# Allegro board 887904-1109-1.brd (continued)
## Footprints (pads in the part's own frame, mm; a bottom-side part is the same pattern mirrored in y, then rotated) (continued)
PG_VG93K_F_HSM_G1D105_505_ND
  rect 1.626x1.626 smd: A1(-20.32,-3.81) A3(-15.24,-3.81) A5(-10.16,-3.81) A7(-5.08,-3.81) A9(0,-3.81) A11(5.08,-3.81) A13(10.16,-3.81) A15(15.24,-3.81) A17(20.32,-3.81) B2(-17.78,-1.27) B4(-12.7,-1.27) B6(-7.62,-1.27) B8(-2.54,-1.27) B10(2.54,-1.27) B12(7.62,-1.27) B14(12.7,-1.27) B16(17.78,-1.27) C1(-20.32,1.27) C3(-15.24,1.27) C5(-10.16,1.27) C7(-5.08,1.27) C9(0,1.27) C11(5.08,1.27) C13(10.16,1.27) C15(15.24,1.27) C17(20.32,1.27) D2(-17.78,3.81) D4(-12.7,3.81) D6(-7.62,3.81) D8(-2.54,3.81) D10(2.54,3.81) D12(7.62,3.81) D14(12.7,3.81) D16(17.78,3.81)
  round 1.626 smd: A2(-17.78,-3.81) A4(-12.7,-3.81) A6(-7.62,-3.81) A8(-2.54,-3.81) A10(2.54,-3.81) A12(7.62,-3.81) A14(12.7,-3.81) A16(17.78,-3.81) B1(-20.32,-1.27) B3(-15.24,-1.27) B5(-10.16,-1.27) B7(-5.08,-1.27) B9(0,-1.27) B11(5.08,-1.27) B13(10.16,-1.27) B15(15.24,-1.27) B17(20.32,-1.27) C2(-17.78,1.27) C4(-12.7,1.27) C6(-7.62,1.27) C8(-2.54,1.27) C10(2.54,1.27) C12(7.62,1.27) C14(12.7,1.27) C16(17.78,1.27) D3(-15.24,3.81) D5(-10.16,3.81) D7(-5.08,3.81) D9(0,3.81) D11(5.08,3.81) D13(10.16,3.81) D15(15.24,3.81)
PG_VG93K_F_HSM_G1D106_506_ND
  rect 1.626x1.626 smd: A1(-20.32,-3.81) A3(-15.24,-3.81) A5(-10.16,-3.81) A7(-5.08,-3.81) A9(0,-3.81) A11(5.08,-3.81) A13(10.16,-3.81) A15(15.24,-3.81) A17(20.32,-3.81) B2(-17.78,-1.27) B4(-12.7,-1.27) B6(-7.62,-1.27) B8(-2.54,-1.27) B10(2.54,-1.27) B12(7.62,-1.27) B14(12.7,-1.27) B16(17.78,-1.27) C1(-20.32,1.27) C3(-15.24,1.27) C5(-10.16,1.27) C7(-5.08,1.27) C9(0,1.27) C11(5.08,1.27) C13(10.16,1.27) C15(15.24,1.27) C17(20.32,1.27) D2(-17.78,3.81) D4(-12.7,3.81) D6(-7.62,3.81) D8(-2.54,3.81) D10(2.54,3.81) D12(7.62,3.81) D14(12.7,3.81) D16(17.78,3.81)
  round 1.626 smd: A2(-17.78,-3.81) A4(-12.7,-3.81) A6(-7.62,-3.81) A8(-2.54,-3.81) A10(2.54,-3.81) A12(7.62,-3.81) A14(12.7,-3.81) A16(17.78,-3.81) B1(-20.32,-1.27) B3(-15.24,-1.27) B5(-10.16,-1.27) B7(-5.08,-1.27) B9(0,-1.27) B11(5.08,-1.27) B13(10.16,-1.27) B15(15.24,-1.27) B17(20.32,-1.27) C2(-17.78,1.27) C4(-12.7,1.27) C6(-7.62,1.27) C8(-2.54,1.27) C10(2.54,1.27) C12(7.62,1.27) C14(12.7,1.27) C16(17.78,1.27) D3(-15.24,3.81) D5(-10.16,3.81) D7(-5.08,3.81) D9(0,3.81) D11(5.08,3.81) D13(10.16,3.81) D15(15.24,3.81)
PG_VG93K_F_HSM_G1D107_507_ND
  rect 1.626x1.626 smd: A1(-20.32,-3.81) A3(-15.24,-3.81) A5(-10.16,-3.81) A7(-5.08,-3.81) A9(0,-3.81) A11(5.08,-3.81) A13(10.16,-3.81) A15(15.24,-3.81) A17(20.32,-3.81) B2(-17.78,-1.27) B4(-12.7,-1.27) B6(-7.62,-1.27) B8(-2.54,-1.27) B10(2.54,-1.27) B12(7.62,-1.27) B14(12.7,-1.27) B16(17.78,-1.27) C1(-20.32,1.27) C3(-15.24,1.27) C5(-10.16,1.27) C7(-5.08,1.27) C9(0,1.27) C11(5.08,1.27) C13(10.16,1.27) C15(15.24,1.27) C17(20.32,1.27) D2(-17.78,3.81) D4(-12.7,3.81) D6(-7.62,3.81) D8(-2.54,3.81) D10(2.54,3.81) D12(7.62,3.81) D14(12.7,3.81) D16(17.78,3.81)
  round 1.626 smd: A2(-17.78,-3.81) A4(-12.7,-3.81) A6(-7.62,-3.81) A8(-2.54,-3.81) A10(2.54,-3.81) A12(7.62,-3.81) A14(12.7,-3.81) A16(17.78,-3.81) B1(-20.32,-1.27) B3(-15.24,-1.27) B5(-10.16,-1.27) B7(-5.08,-1.27) B9(0,-1.27) B11(5.08,-1.27) B13(10.16,-1.27) B15(15.24,-1.27) B17(20.32,-1.27) C2(-17.78,1.27) C4(-12.7,1.27) C6(-7.62,1.27) C8(-2.54,1.27) C10(2.54,1.27) C12(7.62,1.27) C14(12.7,1.27) C16(17.78,1.27) D3(-15.24,3.81) D5(-10.16,3.81) D7(-5.08,3.81) D9(0,3.81) D11(5.08,3.81) D13(10.16,3.81) D15(15.24,3.81)
PG_VG93K_F_HSM_G3D117_517_ND
  rect 1.626x1.626 smd: A1(-20.32,-3.81) A3(-15.24,-3.81) A5(-10.16,-3.81) A7(-5.08,-3.81) A9(0,-3.81) A11(5.08,-3.81) A13(10.16,-3.81) A15(15.24,-3.81) A17(20.32,-3.81) B2(-17.78,-1.27) B4(-12.7,-1.27) B6(-7.62,-1.27) B8(-2.54,-1.27) B10(2.54,-1.27) B12(7.62,-1.27) B14(12.7,-1.27) B16(17.78,-1.27) C1(-20.32,1.27) C3(-15.24,1.27) C5(-10.16,1.27) C7(-5.08,1.27) C9(0,1.27) C11(5.08,1.27) C13(10.16,1.27) C15(15.24,1.27) C17(20.32,1.27) D2(-17.78,3.81) D4(-12.7,3.81) D6(-7.62,3.81) D8(-2.54,3.81) D10(2.54,3.81) D12(7.62,3.81) D14(12.7,3.81) D16(17.78,3.81)
  round 1.626 smd: A2(-17.78,-3.81) A4(-12.7,-3.81) A6(-7.62,-3.81) A8(-2.54,-3.81) A10(2.54,-3.81) A12(7.62,-3.81) A14(12.7,-3.81) A16(17.78,-3.81) B1(-20.32,-1.27) B3(-15.24,-1.27) B5(-10.16,-1.27) B7(-5.08,-1.27) B9(0,-1.27) B11(5.08,-1.27) B13(10.16,-1.27) B15(15.24,-1.27) B17(20.32,-1.27) C2(-17.78,1.27) C4(-12.7,1.27) C6(-7.62,1.27) C8(-2.54,1.27) C10(2.54,1.27) C12(7.62,1.27) C14(12.7,1.27) C16(17.78,1.27) D3(-15.24,3.81) D5(-10.16,3.81) D7(-5.08,3.81) D9(0,3.81) D11(5.08,3.81) D13(10.16,3.81) D15(15.24,3.81)
PG_VG93K_F_HSM_G3D118_518_ND
  rect 1.626x1.626 smd: A1(-20.32,-3.81) A3(-15.24,-3.81) A5(-10.16,-3.81) A7(-5.08,-3.81) A9(0,-3.81) A11(5.08,-3.81) A13(10.16,-3.81) A15(15.24,-3.81) A17(20.32,-3.81) B2(-17.78,-1.27) B4(-12.7,-1.27) B6(-7.62,-1.27) B8(-2.54,-1.27) B10(2.54,-1.27) B12(7.62,-1.27) B14(12.7,-1.27) B16(17.78,-1.27) C1(-20.32,1.27) C3(-15.24,1.27) C5(-10.16,1.27) C7(-5.08,1.27) C9(0,1.27) C11(5.08,1.27) C13(10.16,1.27) C15(15.24,1.27) C17(20.32,1.27) D2(-17.78,3.81) D4(-12.7,3.81) D6(-7.62,3.81) D8(-2.54,3.81) D10(2.54,3.81) D12(7.62,3.81) D14(12.7,3.81) D16(17.78,3.81)
  round 1.626 smd: A2(-17.78,-3.81) A4(-12.7,-3.81) A6(-7.62,-3.81) A8(-2.54,-3.81) A10(2.54,-3.81) A12(7.62,-3.81) A14(12.7,-3.81) A16(17.78,-3.81) B1(-20.32,-1.27) B3(-15.24,-1.27) B5(-10.16,-1.27) B7(-5.08,-1.27) B9(0,-1.27) B11(5.08,-1.27) B13(10.16,-1.27) B15(15.24,-1.27) B17(20.32,-1.27) C2(-17.78,1.27) C4(-12.7,1.27) C6(-7.62,1.27) C8(-2.54,1.27) C10(2.54,1.27) C12(7.62,1.27) C14(12.7,1.27) C16(17.78,1.27) D3(-15.24,3.81) D5(-10.16,3.81) D7(-5.08,3.81) D9(0,3.81) D11(5.08,3.81) D13(10.16,3.81) D15(15.24,3.81)
PG_VG93K_F_HSM_G3D119_519_ND
  rect 1.626x1.626 smd: A1(-20.32,-3.81) A3(-15.24,-3.81) A5(-10.16,-3.81) A7(-5.08,-3.81) A9(0,-3.81) A11(5.08,-3.81) A13(10.16,-3.81) A15(15.24,-3.81) A17(20.32,-3.81) B2(-17.78,-1.27) B4(-12.7,-1.27) B6(-7.62,-1.27) B8(-2.54,-1.27) B10(2.54,-1.27) B12(7.62,-1.27) B14(12.7,-1.27) B16(17.78,-1.27) C1(-20.32,1.27) C3(-15.24,1.27) C5(-10.16,1.27) C7(-5.08,1.27) C9(0,1.27) C11(5.08,1.27) C13(10.16,1.27) C15(15.24,1.27) C17(20.32,1.27) D2(-17.78,3.81) D4(-12.7,3.81) D6(-7.62,3.81) D8(-2.54,3.81) D10(2.54,3.81) D12(7.62,3.81) D14(12.7,3.81) D16(17.78,3.81)
  round 1.626 smd: A2(-17.78,-3.81) A4(-12.7,-3.81) A6(-7.62,-3.81) A8(-2.54,-3.81) A10(2.54,-3.81) A12(7.62,-3.81) A14(12.7,-3.81) A16(17.78,-3.81) B1(-20.32,-1.27) B3(-15.24,-1.27) B5(-10.16,-1.27) B7(-5.08,-1.27) B9(0,-1.27) B11(5.08,-1.27) B13(10.16,-1.27) B15(15.24,-1.27) B17(20.32,-1.27) C2(-17.78,1.27) C4(-12.7,1.27) C6(-7.62,1.27) C8(-2.54,1.27) C10(2.54,1.27) C12(7.62,1.27) C14(12.7,1.27) C16(17.78,1.27) D3(-15.24,3.81) D5(-10.16,3.81) D7(-5.08,3.81) D9(0,3.81) D11(5.08,3.81) D13(10.16,3.81) D15(15.24,3.81)
PG_VG93K_F_HSM_G3D121_521_ND
  rect 1.626x1.626 smd: A1(-20.32,-3.81) A3(-15.24,-3.81) A5(-10.16,-3.81) A7(-5.08,-3.81) A9(0,-3.81) A11(5.08,-3.81) A13(10.16,-3.81) A15(15.24,-3.81) A17(20.32,-3.81) B2(-17.78,-1.27) B4(-12.7,-1.27) B6(-7.62,-1.27) B8(-2.54,-1.27) B10(2.54,-1.27) B12(7.62,-1.27) B14(12.7,-1.27) B16(17.78,-1.27) C1(-20.32,1.27) C3(-15.24,1.27) C5(-10.16,1.27) C7(-5.08,1.27) C9(0,1.27) C11(5.08,1.27) C13(10.16,1.27) C15(15.24,1.27) C17(20.32,1.27) D2(-17.78,3.81) D4(-12.7,3.81) D6(-7.62,3.81) D8(-2.54,3.81) D10(2.54,3.81) D12(7.62,3.81) D14(12.7,3.81) D16(17.78,3.81)
  round 1.626 smd: A2(-17.78,-3.81) A4(-12.7,-3.81) A6(-7.62,-3.81) A8(-2.54,-3.81) A10(2.54,-3.81) A12(7.62,-3.81) A14(12.7,-3.81) A16(17.78,-3.81) B1(-20.32,-1.27) B3(-15.24,-1.27) B5(-10.16,-1.27) B7(-5.08,-1.27) B9(0,-1.27) B11(5.08,-1.27) B13(10.16,-1.27) B15(15.24,-1.27) B17(20.32,-1.27) C2(-17.78,1.27) C4(-12.7,1.27) C6(-7.62,1.27) C8(-2.54,1.27) C10(2.54,1.27) C12(7.62,1.27) C14(12.7,1.27) C16(17.78,1.27) D3(-15.24,3.81) D5(-10.16,3.81) D7(-5.08,3.81) D9(0,3.81) D11(5.08,3.81) D13(10.16,3.81) D15(15.24,3.81)
PG_VG93K_F_HSM_G3D122_522_ND
  rect 1.626x1.626 smd: A1(-20.32,-3.81) A3(-15.24,-3.81) A5(-10.16,-3.81) A7(-5.08,-3.81) A9(0,-3.81) A11(5.08,-3.81) A13(10.16,-3.81) A15(15.24,-3.81) A17(20.32,-3.81) B2(-17.78,-1.27) B4(-12.7,-1.27) B6(-7.62,-1.27) B8(-2.54,-1.27) B10(2.54,-1.27) B12(7.62,-1.27) B14(12.7,-1.27) B16(17.78,-1.27) C1(-20.32,1.27) C3(-15.24,1.27) C5(-10.16,1.27) C7(-5.08,1.27) C9(0,1.27) C11(5.08,1.27) C13(10.16,1.27) C15(15.24,1.27) C17(20.32,1.27) D2(-17.78,3.81) D4(-12.7,3.81) D6(-7.62,3.81) D8(-2.54,3.81) D10(2.54,3.81) D12(7.62,3.81) D14(12.7,3.81) D16(17.78,3.81)
  round 1.626 smd: A2(-17.78,-3.81) A4(-12.7,-3.81) A6(-7.62,-3.81) A8(-2.54,-3.81) A10(2.54,-3.81) A12(7.62,-3.81) A14(12.7,-3.81) A16(17.78,-3.81) B1(-20.32,-1.27) B3(-15.24,-1.27) B5(-10.16,-1.27) B7(-5.08,-1.27) B9(0,-1.27) B11(5.08,-1.27) B13(10.16,-1.27) B15(15.24,-1.27) B17(20.32,-1.27) C2(-17.78,1.27) C4(-12.7,1.27) C6(-7.62,1.27) C8(-2.54,1.27) C10(2.54,1.27) C12(7.62,1.27) C14(12.7,1.27) C16(17.78,1.27) D3(-15.24,3.81) D5(-10.16,3.81) D7(-5.08,3.81) D9(0,3.81) D11(5.08,3.81) D13(10.16,3.81) D15(15.24,3.81)
PG_VG93K_F_HSM_G3D123_523_ND
  rect 1.626x1.626 smd: A1(-20.32,-3.81) A3(-15.24,-3.81) A5(-10.16,-3.81) A7(-5.08,-3.81) A9(0,-3.81) A11(5.08,-3.81) A13(10.16,-3.81) A15(15.24,-3.81) A17(20.32,-3.81) B2(-17.78,-1.27) B4(-12.7,-1.27) B6(-7.62,-1.27) B8(-2.54,-1.27) B10(2.54,-1.27) B12(7.62,-1.27) B14(12.7,-1.27) B16(17.78,-1.27) C1(-20.32,1.27) C3(-15.24,1.27) C5(-10.16,1.27) C7(-5.08,1.27) C9(0,1.27) C11(5.08,1.27) C13(10.16,1.27) C15(15.24,1.27) C17(20.32,1.27) D2(-17.78,3.81) D4(-12.7,3.81) D6(-7.62,3.81) D8(-2.54,3.81) D10(2.54,3.81) D12(7.62,3.81) D14(12.7,3.81) D16(17.78,3.81)
  round 1.626 smd: A2(-17.78,-3.81) A4(-12.7,-3.81) A6(-7.62,-3.81) A8(-2.54,-3.81) A10(2.54,-3.81) A12(7.62,-3.81) A14(12.7,-3.81) A16(17.78,-3.81) B1(-20.32,-1.27) B3(-15.24,-1.27) B5(-10.16,-1.27) B7(-5.08,-1.27) B9(0,-1.27) B11(5.08,-1.27) B13(10.16,-1.27) B15(15.24,-1.27) B17(20.32,-1.27) C2(-17.78,1.27) C4(-12.7,1.27) C6(-7.62,1.27) C8(-2.54,1.27) C10(2.54,1.27) C12(7.62,1.27) C14(12.7,1.27) C16(17.78,1.27) D3(-15.24,3.81) D5(-10.16,3.81) D7(-5.08,3.81) D9(0,3.81) D11(5.08,3.81) D13(10.16,3.81) D15(15.24,3.81)
PG_VG93K_PF_DPS32_G8D225
  rect 1.778x1.778 hole 0.711: A1(20.32,3.81) A3(15.24,3.81) A5(10.16,3.81) A7(5.08,3.81) A9(0,3.81) A11(-5.08,3.81) A13(-10.16,3.81) A15(-15.24,3.81) B2(17.78,1.27) B4(12.7,1.27) B6(7.62,1.27) B8(2.54,1.27) B10(-2.54,1.27) B12(-7.62,1.27) B14(-12.7,1.27) B16(-17.78,1.27) C1(20.32,-1.27) C3(15.24,-1.27) C5(10.16,-1.27) C7(5.08,-1.27) C9(0,-1.27) C11(-5.08,-1.27) C13(-10.16,-1.27) C15(-15.24,-1.27) D2(17.78,-3.81) D4(12.7,-3.81) D6(7.62,-3.81) D8(2.54,-3.81) D10(-2.54,-3.81) D12(-7.62,-3.81) D14(-12.7,-3.81) D16(-17.78,-3.81)
  round 1.524 hole 0.711: A2(17.78,3.81) A4(12.7,3.81) A6(7.62,3.81) A8(2.54,3.81) A10(-2.54,3.81) A12(-7.62,3.81) A14(-12.7,3.81) A16(-17.78,3.81) A17(-20.32,3.81) B1(20.32,1.27) B3(15.24,1.27) B5(10.16,1.27) B7(5.08,1.27) B9(0,1.27) B11(-5.08,1.27) B13(-10.16,1.27) B15(-15.24,1.27) B17(-20.32,1.27) C2(17.78,-1.27) C4(12.7,-1.27) C6(7.62,-1.27) C8(2.54,-1.27) C10(-2.54,-1.27) C12(-7.62,-1.27) C14(-12.7,-1.27) C16(-17.78,-1.27) C17(-20.32,-1.27) D1(20.32,-3.81) D3(15.24,-3.81) D5(10.16,-3.81) D7(5.08,-3.81) D9(0,-3.81) D11(-5.08,-3.81) D13(-10.16,-3.81) D15(-15.24,-3.81) D17(-20.32,-3.81)
PG_VG93K_PF_DPS32_G8D229
  rect 1.778x1.778 hole 0.711: A1(20.32,3.81) A3(15.24,3.81) A5(10.16,3.81) A7(5.08,3.81) A9(0,3.81) A11(-5.08,3.81) A13(-10.16,3.81) A15(-15.24,3.81) B2(17.78,1.27) B4(12.7,1.27) B6(7.62,1.27) B8(2.54,1.27) B10(-2.54,1.27) B12(-7.62,1.27) B14(-12.7,1.27) B16(-17.78,1.27) C1(20.32,-1.27) C3(15.24,-1.27) C5(10.16,-1.27) C7(5.08,-1.27) C9(0,-1.27) C11(-5.08,-1.27) C13(-10.16,-1.27) C15(-15.24,-1.27) D2(17.78,-3.81) D4(12.7,-3.81) D6(7.62,-3.81) D8(2.54,-3.81) D10(-2.54,-3.81) D12(-7.62,-3.81) D14(-12.7,-3.81) D16(-17.78,-3.81)
  round 1.524 hole 0.711: A2(17.78,3.81) A4(12.7,3.81) A6(7.62,3.81) A8(2.54,3.81) A10(-2.54,3.81) A12(-7.62,3.81) A14(-12.7,3.81) A16(-17.78,3.81) A17(-20.32,3.81) B1(20.32,1.27) B3(15.24,1.27) B5(10.16,1.27) B7(5.08,1.27) B9(0,1.27) B11(-5.08,1.27) B13(-10.16,1.27) B15(-15.24,1.27) B17(-20.32,1.27) C2(17.78,-1.27) C4(12.7,-1.27) C6(7.62,-1.27) C8(2.54,-1.27) C10(-2.54,-1.27) C12(-7.62,-1.27) C14(-12.7,-1.27) C16(-17.78,-1.27) C17(-20.32,-1.27) D1(20.32,-3.81) D3(15.24,-3.81) D5(10.16,-3.81) D7(5.08,-3.81) D9(0,-3.81) D11(-5.08,-3.81) D13(-10.16,-3.81) D15(-15.24,-3.81) D17(-20.32,-3.81)
PG_VG93K_PF_DPS32_G8D425
  rect 1.778x1.778 hole 0.711: A1(20.32,3.81) A3(15.24,3.81) A5(10.16,3.81) A7(5.08,3.81) A9(0,3.81) A11(-5.08,3.81) A13(-10.16,3.81) A15(-15.24,3.81) B2(17.78,1.27) B4(12.7,1.27) B6(7.62,1.27) B8(2.54,1.27) B10(-2.54,1.27) B12(-7.62,1.27) B14(-12.7,1.27) B16(-17.78,1.27) C1(20.32,-1.27) C3(15.24,-1.27) C5(10.16,-1.27) C7(5.08,-1.27) C9(0,-1.27) C11(-5.08,-1.27) C13(-10.16,-1.27) C15(-15.24,-1.27) D2(17.78,-3.81) D4(12.7,-3.81) D6(7.62,-3.81) D8(2.54,-3.81) D10(-2.54,-3.81) D12(-7.62,-3.81) D14(-12.7,-3.81) D16(-17.78,-3.81)
  round 1.524 hole 0.711: A2(17.78,3.81) A4(12.7,3.81) A6(7.62,3.81) A8(2.54,3.81) A10(-2.54,3.81) A12(-7.62,3.81) A14(-12.7,3.81) A16(-17.78,3.81) A17(-20.32,3.81) B1(20.32,1.27) B3(15.24,1.27) B5(10.16,1.27) B7(5.08,1.27) B9(0,1.27) B11(-5.08,1.27) B13(-10.16,1.27) B15(-15.24,1.27) B17(-20.32,1.27) C2(17.78,-1.27) C4(12.7,-1.27) C6(7.62,-1.27) C8(2.54,-1.27) C10(-2.54,-1.27) C12(-7.62,-1.27) C14(-12.7,-1.27) C16(-17.78,-1.27) C17(-20.32,-1.27) D1(20.32,-3.81) D3(15.24,-3.81) D5(10.16,-3.81) D7(5.08,-3.81) D9(0,-3.81) D11(-5.08,-3.81) D13(-10.16,-3.81) D15(-15.24,-3.81) D17(-20.32,-3.81)
PG_VG93K_PF_DPS32_G8D429
  rect 1.778x1.778 hole 0.711: A1(20.32,3.81) A3(15.24,3.81) A5(10.16,3.81) A7(5.08,3.81) A9(0,3.81) A11(-5.08,3.81) A13(-10.16,3.81) A15(-15.24,3.81) B2(17.78,1.27) B4(12.7,1.27) B6(7.62,1.27) B8(2.54,1.27) B10(-2.54,1.27) B12(-7.62,1.27) B14(-12.7,1.27) B16(-17.78,1.27) C1(20.32,-1.27) C3(15.24,-1.27) C5(10.16,-1.27) C7(5.08,-1.27) C9(0,-1.27) C11(-5.08,-1.27) C13(-10.16,-1.27) C15(-15.24,-1.27) D2(17.78,-3.81) D4(12.7,-3.81) D6(7.62,-3.81) D8(2.54,-3.81) D10(-2.54,-3.81) D12(-7.62,-3.81) D14(-12.7,-3.81) D16(-17.78,-3.81)
  round 1.524 hole 0.711: A2(17.78,3.81) A4(12.7,3.81) A6(7.62,3.81) A8(2.54,3.81) A10(-2.54,3.81) A12(-7.62,3.81) A14(-12.7,3.81) A16(-17.78,3.81) A17(-20.32,3.81) B1(20.32,1.27) B3(15.24,1.27) B5(10.16,1.27) B7(5.08,1.27) B9(0,1.27) B11(-5.08,1.27) B13(-10.16,1.27) B15(-15.24,1.27) B17(-20.32,1.27) C2(17.78,-1.27) C4(12.7,-1.27) C6(7.62,-1.27) C8(2.54,-1.27) C10(-2.54,-1.27) C12(-7.62,-1.27) C14(-12.7,-1.27) C16(-17.78,-1.27) C17(-20.32,-1.27) D1(20.32,-3.81) D3(15.24,-3.81) D5(10.16,-3.81) D7(5.08,-3.81) D9(0,-3.81) D11(-5.08,-3.81) D13(-10.16,-3.81) D15(-15.24,-3.81) D17(-20.32,-3.81)
R0402
  custom 0.15x0.15 smd: 1(-0.5,0) 2(0.5,0)
R0603
  rect 0.889x0.889 smd: 1(-0.85,0) 2(0.85,0)
RL_G6K2FRT_8P_5V_GR
  rect 0.813x2.54 smd: 1(-3.75,-4) 2(-0.55,-4) 3(1.65,-4) 4(3.85,-4) 5(3.85,4) 6(1.65,4) 7(-0.55,4) 8(-3.75,4) G2(-1.65,-4) G3(0.55,-4) G4(2.75,-4) G7(2.75,4) G8(0.55,4) G9(-1.65,4)
  rect 1.092x2.54 smd: G1(-5.1,-4) G5(5.2,-4) G6(5.2,4) G10(-5.1,4)
RL_NECEC2_10P_5V
  rect 1.626x1.626 hole 1.041: 1(6.35,2.54)
  round 1.626 hole 1.041: 3(1.27,2.54) 4(-1.27,2.54) 5(-3.81,2.54) 8(-3.81,-2.54) 9(-1.27,-2.54) 10(1.27,-2.54) 12(6.35,-2.54)
RL_NECUA2_5V_V3
  rect 1.626x1.626 hole 1.041: 1(3.6,1.6)
  round 1.626 hole 1.041: 2(0.4,1.6) 3(-1.8,1.6) 4(-4,1.6) 5(-4,-1.6) 6(-1.8,-1.6) 7(0.4,-1.6) 8(3.6,-1.6)
SK_SO8_150_1P27MM_LOTES
  rect 0.508x4.064 smd: 1(-1.91,-4.05) 2(-0.64,-4.05) 3(0.63,-4.05) 4(1.9,-4.05) 5(1.91,4.05) 6(0.64,4.05) 7(-0.63,4.05) 8(-1.9,4.05)
SK_WFBGA75P_0P65MM_JG_887904
  round 0.508 hole 1.61 unplated: (-17,17) (-17,-17) (17,17) (17,-17)
  round 0.5 smd: A1(-4.55,1.3) A2(-3.9,1.3) A3(-3.25,1.3) A4(-2.6,1.3) A5(-1.95,1.3) A6(-1.3,1.3) A7(-0.65,1.3) A8(0,1.3) A9(0.65,1.3) A10(1.3,1.3) A11(1.95,1.3) A12(2.6,1.3) A13(3.25,1.3) A14(3.9,1.3) A15(4.55,1.3) B1(-4.55,0.65) B2(-3.9,0.65) B3(-3.25,0.65) B4(-2.6,0.65) B5(-1.95,0.65) B6(-1.3,0.65) B7(-0.65,0.65) B8(0,0.65) B9(0.65,0.65) B10(1.3,0.65) B11(1.95,0.65) B12(2.6,0.65) B13(3.25,0.65) B14(3.9,0.65) B15(4.55,0.65) C1(-4.55,0) C2(-3.9,0) C3(-3.25,0) C4(-2.6,0) C5(-1.95,0) C6(-1.3,0) C7(-0.65,0) C8(0,0) C9(0.65,0) C10(1.3,0) C11(1.95,0) C12(2.6,0) C13(3.25,0) C14(3.9,0) C15(4.55,0) D1(-4.55,-0.65) D2(-3.9,-0.65) D3(-3.25,-0.65) D4(-2.6,-0.65) D5(-1.95,-0.65) D6(-1.3,-0.65) D7(-0.65,-0.65) D8(0,-0.65) D9(0.65,-0.65) D10(1.3,-0.65) D11(1.95,-0.65) D12(2.6,-0.65) D13(3.25,-0.65) D14(3.9,-0.65) D15(4.55,-0.65) E1(-4.55,-1.3) E2(-3.9,-1.3) E3(-3.25,-1.3) E4(-2.6,-1.3) E5(-1.95,-1.3) E6(-1.3,-1.3) E7(-0.65,-1.3) E8(0,-1.3) E9(0.65,-1.3) E10(1.3,-1.3) E11(1.95,-1.3) E12(2.6,-1.3) E13(3.25,-1.3) E14(3.9,-1.3) E15(4.55,-1.3)
  round 7 hole 4.293: NUT1(-12.7,12.7) NUT2(12.7,12.7) NUT3(-12.7,-12.7) NUT4(12.7,-12.7)
SO8_215X127MM
  rect 1.778x0.762 smd: 1(-2.731,2.032) 4(-2.731,-2.032) 5(2.731,-2.032) 8(2.731,2.032)
  rect 1.778x0.61 smd: 2(-2.731,0.635) 3(-2.731,-0.635) 6(2.731,-0.635) 7(2.731,0.635)
SOCKET_CODE
  round 0.051 smd: 1(0,0)
SOCKETBASE_294X213_888003
  round 11.024 hole 7.01: NUT1(-70,70) NUT2(70,70) NUT3(-70,-70) NUT4(70,-70)
SW_DIPX1_2P_H5MM
  round 1.626 hole 1.041: 1(0,-3.81) 2(0,3.81)
TP_040_T
  round 1.016 smd: 1(0,0)
TP_060_040
  round 1.524 hole 1.016: 1(0,0)
TPL_040_014_TB
  round 1.016 hole 0.356: 1(0,0)

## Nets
GND: BD29.1 BD30.1 BD31.1 BD32.1 BD33.1 BD34.1 BD35.1 BD36.1 BD37.1 BD38.1 BD39.1 BD40.1 BD41.1 BD42.1 BD43.1 BD44.1 C1.2 C55.1 C67.2 C69.2 C70.2 C71.2 C73.2 C75.2 C77.2 C79.2 C81.2 C83.2 C85.2 C87.2 C89.2 C90.2 C91.2 C92.2 C93.2 C94.2 C95.2 C96.2 CA1.2 CA2.2 CA3.2 CA4.2 CA5.2 CA6.2 CA7.2 CA8.2 CA9.2 CA10.2 CA12.2 CA13.2 CA14.2 CC1.2 CC2.2 CC3.2 CC4.2 CC5.2 CC6.2 CC7.2 CC8.2 CC9.2 CC10.2 CC11.2 CC12.2 CC13.2 CC14.2 CC15.2 CD1.2 CD2.2 CD3.2 CD4.2 CD5.2 CD6.2 CD7.2 CD8.2 CD9.2 CD10.2 CD11.2 CD12.2 CD13.2 CD14.2 CD15.2 CSDPS225.B2 CSDPS225.B4 CSDPS225.B6 CSDPS225.B8 CSDPS225.B10 CSDPS225.B12 CSDPS225.B14 CSDPS225.B16 CSDPS225.C1 CSDPS225.C3 CSDPS225.C5 CSDPS225.C7 CSDPS225.C9 CSDPS225.C11 CSDPS225.C13 CSDPS225.C15 CSDPS229.B2 CSDPS229.B4 CSDPS229.B6 CSDPS229.B8 CSDPS229.B10 CSDPS229.B12 CSDPS229.B14 CSDPS229.B16 CSDPS229.C1 CSDPS229.C3 CSDPS229.C5 CSDPS229.C7 CSDPS229.C9 CSDPS229.C11 CSDPS229.C13 CSDPS229.C15 CSDPS425.B2 CSDPS425.B4 CSDPS425.B6 CSDPS425.B8 CSDPS425.B10 CSDPS425.B12 CSDPS425.B14 CSDPS425.B16 CSDPS425.C1 CSDPS425.C3 CSDPS425.C5 CSDPS425.C7 CSDPS425.C9 CSDPS425.C11 CSDPS425.C13 CSDPS425.C15 CSDPS429.B2 CSDPS429.B4 CSDPS429.B6 CSDPS429.B8 CSDPS429.B10 CSDPS429.B12 CSDPS429.B14 CSDPS429.B16 CSDPS429.C1 CSDPS429.C3 CSDPS429.C5 CSDPS429.C7 CSDPS429.C9 CSDPS429.C11 CSDPS429.C13 CSDPS429.C15 D104.A1 D104.A2 D104.A3 D104.A4 D104.A5 D104.A6 D104.A7 D104.A8 D104.A9 D104.A10 D104.A11 D104.A12 D104.A13 D104.A14 D104.A15 D104.A16 D104.B1 D104.B2 D104.B3 D104.B4 D104.B5 D104.B6 D104.B7 D104.B8 D104.B9 D104.B10 D104.B11 D104.B12 D104.B13 D104.B14 D104.B15 D104.B16 D108.A1 D108.A2 D108.A3 D108.A4 D108.A5 D108.A6 D108.A7 D108.A8 D108.A9 D108.A10 D108.A11 D108.A12 D108.A13 D108.A14 D108.A15 D108.A16 D108.B1 D108.B2 D108.B3 D108.B4 D108.B5 D108.B6 D108.B7 D108.B8 D108.B9 D108.B10 D108.B11 D108.B12 D108.B13 D108.B14 D108.B15 D108.B16 D109.A1 D109.A2 D109.A3 D109.A4 D109.A5 D109.A6 D109.A7 D109.A8 D109.A9 D109.A10 D109.A11 D109.A12 D109.A13 D109.A14 D109.A15 D109.A16 D109.B1 D109.B2 D109.B3 D109.B4 D109.B5 D109.B6 D109.B7 D109.B8 D109.B9 D109.B10 D109.B11 D109.B12 D109.B13 D109.B14 D109.B15 D109.B16 D110.A1 D110.A2 D110.A3 D110.A4 D110.A5 D110.A6 D110.A7 D110.A8 D110.A9 D110.A10 D110.A11 D110.A12 D110.A13 D110.A14 D110.A15 D110.A16 D110.B1 D110.B2 D110.B3 D110.B4 D110.B5 D110.B6 D110.B7 D110.B8 D110.B9 D110.B10 D110.B11 D110.B12 D110.B13 D110.B14 D110.B15 D110.B16 D111.A1 D111.A2 D111.A3 D111.A4 D111.A5 D111.A6 D111.A7 D111.A8 D111.A9 D111.A10 D111.A11 D111.A12 D111.A13 D111.A14 D111.A15 D111.A16 D111.B1 D111.B2 D111.B3 D111.B4 D111.B5 D111.B6 D111.B7 D111.B8 D111.B9 D111.B10 D111.B11 D111.B12 D111.B13 D111.B14 D111.B15 D111.B16 D112.A1 D112.A2 D112.A3 D112.A4 D112.A5 D112.A6 D112.A7 D112.A8 D112.A9 D112.A10 D112.A11 D112.A12 D112.A13 D112.A14 D112.A15 D112.A16 D112.B1 D112.B2 D112.B3 D112.B4 D112.B5 D112.B6 D112.B7 D112.B8 D112.B9 D112.B10 D112.B11 D112.B12 D112.B13 D112.B14 D112.B15 D112.B16 D113.A1 D113.A2 D113.A3 D113.A4 D113.A5 D113.A6 D113.A7 D113.A8 D113.A9 D113.A10 D113.A11 D113.A12 D113.A13 D113.A14 D113.A15 D113.A16 D113.B1 D113.B2 D113.B3 D113.B4 D113.B5 D113.B6 D113.B7 D113.B8 D113.B9 D113.B10 D113.B11 D113.B12 D113.B13 D113.B14 D113.B15 D113.B16 D114.A1 D114.A2 D114.A3 D114.A4 D114.A5 D114.A6 D114.A7 D114.A8 D114.A9 D114.A10 D114.A11 D114.A12 D114.A13 D114.A14 D114.A15 D114.A16 D114.B1 D114.B2 D114.B3 D114.B4 D114.B5 D114.B6 D114.B7 D114.B8 D114.B9 D114.B10 D114.B11 D114.B12 D114.B13 D114.B14 D114.B15 D114.B16 D115.A1 D115.A2 D115.A3 D115.A4 D115.A5 D115.A6 D115.A7 D115.A8 D115.A9 D115.A10 D115.A11 D115.A12 D115.A13 D115.A14 D115.A15 D115.A16 D115.B1 D115.B2 D115.B3 D115.B4 D115.B5 D115.B6 D115.B7 D115.B8 D115.B9 D115.B10 D115.B11 D115.B12 D115.B13 D115.B14 D115.B15 D115.B16 D116.A1 D116.A2 D116.A3 D116.A4 D116.A5 D116.A6 D116.A7 D116.A8 D116.A9 D116.A10 D116.A11 D116.A12 D116.A13 D116.A14 D116.A15 D116.A16 D116.B1 D116.B2 D116.B3 D116.B4 D116.B5 D116.B6 D116.B7 D116.B8 D116.B9 D116.B10 D116.B11 D116.B12 D116.B13 D116.B14 D116.B15 D116.B16 D120.A1 D120.A2 D120.A3 D120.A4 D120.A5 D120.A6 D120.A7 D120.A8 D120.A9 D120.A10 D120.A11 D120.A12 D120.A13 D120.A14 D120.A15 D120.A16 D120.B1 D120.B2 D120.B3 D120.B4 D120.B5 D120.B6 D120.B7 D120.B8 D120.B9 D120.B10 D120.B11 D120.B12 D120.B13 D120.B14 D120.B15 D120.B16 D124.A1 D124.A2 D124.A3 D124.A4 D124.A5 D124.A6 D124.A7 D124.A8 D124.A9 D124.A10 D124.A11 D124.A12 D124.A13 D124.A14 D124.A15 D124.A16 D124.B1 D124.B2 D124.B3 D124.B4 D124.B5 D124.B6 D124.B7 D124.B8 D124.B9 D124.B10 D124.B11 D124.B12 D124.B13 D124.B14 D124.B15 D124.B16 D125.A1 D125.A2 D125.A3 D125.A4 D125.A5 D125.A6 D125.A7 D125.A8 D125.A9 D125.A10 D125.A11 D125.A12 D125.A13 D125.A14 D125.A15 D125.A16 D125.B1 D125.B2 D125.B3 D125.B4 D125.B5 D125.B6 D125.B7 D125.B8 D125.B9 D125.B10 D125.B11 D125.B12 D125.B13 D125.B14 D125.B15 D125.B16 D126.A1 D126.A2 D126.A3 D126.A4 D126.A5 D126.A6 D126.A7 D126.A8 D126.A9 D126.A10 D126.A11 D126.A12 D126.A13 D126.A14 D126.A15 D126.A16 D126.B1 D126.B2 D126.B3 D126.B4 D126.B5 D126.B6 D126.B7 D126.B8 D126.B9 D126.B10 D126.B11 D126.B12 D126.B13 D126.B14 D126.B15 D126.B16 D127.A1 D127.A2 D127.A3 D127.A4 D127.A5 D127.A6 D127.A7 D127.A8 D127.A9 D127.A10 D127.A11 D127.A12 D127.A13 D127.A14 D127.A15 D127.A16 D127.B1 D127.B2 D127.B3 D127.B4 D127.B5 D127.B6 D127.B7 D127.B8 D127.B9 D127.B10 D127.B11 D127.B12 D127.B13 D127.B14 D127.B15 D127.B16 D128.A1 D128.A2 D128.A3 D128.A4 D128.A5 D128.A6 D128.A7 D128.A8 D128.A9 D128.A10 D128.A11 D128.A12 D128.A13 D128.A14 D128.A15 D128.A16 D128.B1 D128.B2 D128.B3 D128.B4 D128.B5 D128.B6 D128.B7 D128.B8 D128.B9 D128.B10 D128.B11 D128.B12 D128.B13 D128.B14 D128.B15 D128.B16 D129.A1 D129.A2 D129.A3 D129.A4 D129.A5 D129.A6 D129.A7 D129.A8 D129.A9 D129.A10 D129.A11 D129.A12 D129.A13 D129.A14 D129.A15 D129.A16 D129.B1 D129.B2 D129.B3 D129.B4 D129.B5 D129.B6 D129.B7 D129.B8 D129.B9 D129.B10 D129.B11 D129.B12 D129.B13 D129.B14 D129.B15 D129.B16 D130.A1 D130.A2 D130.A3 D130.A4 D130.A5 D130.A6 D130.A7 D130.A8 D130.A9 D130.A10 D130.A11 D130.A12 D130.A13 D130.A14 D130.A15 D130.A16 D130.B1 D130.B2 D130.B3 D130.B4 D130.B5 D130.B6 D130.B7 D130.B8 D130.B9 D130.B10 D130.B11 D130.B12 D130.B13 D130.B14 D130.B15 D130.B16 D131.A1 D131.A2 D131.A3 D131.A4 D131.A5 D131.A6 D131.A7 D131.A8 D131.A9 D131.A10 D131.A11 D131.A12 D131.A13 D131.A14 D131.A15 D131.A16 D131.B1 D131.B2 D131.B3 D131.B4 D131.B5 D131.B6 D131.B7 D131.B8 D131.B9 D131.B10 D131.B11 D131.B12 D131.B13 D131.B14 D131.B15 D131.B16 D132.A1 D132.A2 D132.A3 D132.A4 D132.A5 D132.A6 D132.A7 D132.A8 D132.A9 D132.A10 D132.A11 D132.A12 D132.A13 D132.A14 D132.A15 D132.A16 D132.B1 D132.B2 D132.B3 D132.B4 D132.B5 D132.B6 D132.B7 D132.B8 D132.B9 D132.B10 D132.B11 D132.B12 D132.B13 D132.B14 D132.B15 D132.B16 D201.A1 D201.A2 D201.A3 D201.A4 D201.A5 D201.A6 D201.A7 D201.A8 D201.A9 D201.A10 D201.A11 D201.A12 D201.A13 D201.A14 D201.A15 D201.A16 D201.B1 D201.B2 D201.B3 D201.B4 D201.B5 D201.B6 D201.B7 D201.B8 D201.B9 D201.B10 D201.B11 D201.B12 D201.B13 D201.B14 D201.B15 D201.B16 D202.A1 D202.A2 D202.A3 D202.A4 D202.A5 D202.A6 D202.A7 D202.A8 D202.A9 D202.A10 D202.A11 D202.A12 D202.A13 D202.A14 D202.A15 D202.A16 D202.B1 D202.B2 D202.B3 D202.B4 D202.B5 D202.B6 D202.B7 D202.B8 D202.B9 D202.B10 D202.B11 D202.B12 D202.B13 D202.B14 D202.B15 D202.B16 D203.A1 D203.A2 D203.A3 D203.A4 D203.A5 D203.A6 D203.A7 D203.A8 D203.A9 D203.A10 D203.A11 D203.A12 D203.A13 D203.A14 D203.A15 D203.A16 D203.B1 D203.B2 D203.B3 D203.B4 D203.B5 D203.B6 D203.B7 D203.B8 D203.B9 D203.B10 D203.B11 D203.B12 D203.B13 D203.B14 D203.B15 D203.B16 D204.A1 D204.A2 D204.A3 D204.A4 D204.A5 D204.A6 D204.A7 D204.A8 D204.A9 D204.A10 D204.A11 D204.A12 D204.A13 D204.A14 D204.A15 D204.A16 D204.B1 D204.B2 D204.B3 D204.B4 D204.B5 D204.B6 D204.B7 D204.B8 D204.B9 D204.B10 D204.B11 D204.B12 D204.B13 D204.B14 D204.B15 D204.B16 D205.A1 D205.A2 D205.A3 D205.A4 D205.A5 D205.A6 D205.A7 D205.A8 D205.A9 D205.A10 D205.A11 D205.A12 D205.A13 D205.A14 D205.A15 D205.A16 D205.B1 D205.B2 D205.B3 D205.B4 D205.B5 D205.B6 D205.B7 D205.B8 D205.B9 D205.B10 D205.B11 D205.B12 D205.B13 D205.B14 D205.B15 D205.B16 D206.A1 D206.A2 D206.A3 D206.A4 D206.A5 D206.A6 D206.A7 D206.A8 D206.A9 D206.A10 D206.A11 D206.A12 D206.A13 D206.A14 D206.A15 D206.A16 D206.B1 D206.B2 D206.B3 D206.B4 D206.B5 D206.B6 D206.B7 D206.B8 D206.B9 D206.B10 D206.B11 D206.B12 D206.B13 D206.B14 D206.B15 D206.B16 D207.A1 D207.A2 D207.A3 D207.A4 D207.A5 D207.A6 D207.A7 D207.A8 D207.A9 D207.A10 D207.A11 D207.A12 D207.A13 D207.A14 D207.A15 D207.A16 D207.B1 D207.B2 D207.B3 D207.B4 D207.B5 D207.B6 D207.B7 D207.B8 D207.B9 D207.B10 D207.B11 D207.B12 D207.B13 D207.B14 D207.B15 D207.B16 D208.A1 D208.A2 D208.A3 D208.A4 D208.A5 D208.A6 D208.A7 D208.A8 D208.A9 D208.A10 D208.A11 D208.A12 D208.A13 D208.A14 D208.A15 D208.A16 D208.B1 D208.B2 D208.B3 D208.B4 D208.B5 D208.B6 D208.B7 D208.B8 D208.B9 D208.B10 D208.B11 D208.B12 D208.B13 D208.B14 D208.B15 D208.B16 D209.A1 D209.A2 D209.A3 D209.A4 D209.A5 D209.A6 D209.A7 D209.A8 D209.A9 D209.A10 D209.A11 D209.A12 D209.A13 D209.A14 D209.A15 D209.A16 D209.B1 D209.B2 D209.B3 D209.B4 D209.B5 D209.B6 D209.B7 D209.B8 D209.B9 D209.B10 D209.B11 D209.B12 D209.B13 D209.B14 D209.B15 D209.B16 D210.A1 D210.A2 D210.A3 D210.A4 D210.A5 D210.A6 D210.A7 D210.A8 D210.A9 D210.A10 D210.A11 D210.A12 D210.A13 D210.A14 D210.A15 D210.A16 D210.B1 D210.B2 D210.B3 D210.B4 D210.B5 D210.B6 D210.B7 D210.B8 D210.B9 D210.B10 D210.B11 D210.B12 D210.B13 D210.B14 D210.B15 D210.B16 D211.A1 D211.A2 D211.A3 D211.A4 D211.A5 D211.A6 D211.A7 D211.A8 D211.A9 D211.A10 D211.A11 D211.A12 D211.A13 D211.A14 D211.A15 D211.A16 D211.B1 D211.B2 D211.B3 D211.B4 D211.B5 D211.B6 D211.B7 D211.B8 D211.B9 D211.B10 D211.B11 D211.B12 D211.B13 D211.B14 D211.B15 D211.B16 D212.A1 D212.A2 D212.A3 D212.A4 D212.A5 D212.A6 D212.A7 D212.A8 D212.A9 D212.A10 D212.A11 D212.A12 D212.A13 D212.A14 D212.A15 D212.A16 D212.B1 D212.B2 D212.B3 D212.B4 D212.B5 D212.B6 D212.B7 D212.B8 D212.B9 D212.B10 D212.B11 D212.B12 D212.B13 D212.B14 D212.B15 D212.B16 D213.A1 D213.A2 D213.A3 D213.A4 D213.A5 D213.A6 D213.A7 D213.A8 D213.A9 D213.A10 D213.A11 D213.A12 D213.A13 D213.A14 D213.A15 D213.A16 D213.B1 D213.B2 D213.B3 D213.B4 D213.B5 D213.B6 D213.B7 D213.B8 D213.B9 D213.B10 D213.B11 D213.B12 D213.B13 D213.B14 D213.B15 D213.B16 D214.A1 D214.A2 D214.A3 D214.A4 D214.A5 D214.A6 D214.A7 D214.A8 D214.A9 D214.A10 D214.A11 D214.A12 D214.A13 D214.A14 D214.A15 D214.A16 D214.B1 D214.B2 D214.B3 D214.B4 D214.B5 D214.B6 D214.B7 D214.B8 D214.B9 D214.B10 D214.B11 D214.B12 D214.B13 D214.B14 D214.B15 D214.B16 D215.A1 D215.A2 D215.A3 D215.A4 D215.A5 D215.A6 D215.A7 D215.A8 D215.A9 D215.A10 D215.A11 D215.A12 D215.A13 D215.A14 D215.A15 D215.A16 D215.B1 D215.B2 D215.B3 D215.B4 D215.B5 D215.B6 D215.B7 D215.B8 D215.B9 D215.B10 D215.B11 D215.B12 D215.B13 D215.B14 D215.B15 D215.B16 D216.A1 D216.A2 D216.A3 D216.A4 D216.A5 D216.A6 D216.A7 D216.A8 D216.A9 D216.A10 D216.A11 D216.A12 D216.A13 D216.A14 D216.A15 D216.A16 D216.B1 D216.B2 D216.B3 D216.B4 D216.B5 D216.B6 D216.B7 D216.B8 D216.B9 D216.B10 D216.B11 D216.B12 D216.B13 D216.B14 D216.B15 D216.B16 D217.A1 D217.A2 D217.A3 D217.A4 D217.A5 D217.A6 D217.A7 D217.A8 D217.A9 D217.A10 D217.A11 D217.A12 D217.A13 D217.A14 D217.A15 D217.A16 D217.B1 D217.B2 D217.B3 D217.B4 D217.B5 D217.B6 D217.B7 D217.B8 D217.B9 D217.B10 D217.B11 D217.B12 D217.B13 D217.B14 D217.B15 D217.B16 D218.A1 D218.A2 D218.A3 D218.A4 D218.A5 D218.A6 D218.A7 D218.A8 D218.A9 D218.A10 D218.A11 D218.A12 D218.A13 D218.A14 D218.A15 D218.A16 D218.B1 D218.B2 D218.B3 D218.B4 D218.B5 D218.B6 D218.B7 D218.B8 D218.B9 D218.B10 D218.B11 D218.B12 D218.B13 D218.B14 D218.B15 D218.B16 D219.A1 D219.A2 D219.A3 D219.A4 D219.A5 D219.A6 D219.A7 D219.A8 D219.A9 D219.A10 D219.A11 D219.A12 D219.A13 D219.A14 D219.A15 D219.A16 D219.B1 D219.B2 D219.B3 D219.B4 D219.B5 D219.B6 D219.B7 D219.B8 D219.B9 D219.B10 D219.B11 D219.B12 D219.B13 D219.B14 D219.B15 D219.B16 D220.A1 D220.A2 D220.A3 D220.A4 D220.A5 D220.A6 D220.A7 D220.A8 D220.A9 D220.A10 D220.A11 D220.A12 D220.A13 D220.A14 D220.A15 D220.A16 D220.B1 D220.B2 D220.B3 D220.B4 D220.B5 D220.B6 D220.B7 D220.B8 D220.B9 D220.B10 D220.B11 D220.B12 D220.B13 D220.B14 D220.B15 D220.B16 D221.A1 D221.A2 D221.A3 D221.A4 D221.A5 D221.A6 D221.A7 D221.A8 D221.A9 D221.A10 D221.A11 D221.A12 D221.A13 D221.A14 D221.A15 D221.A16 D221.B1 D221.B2 D221.B3 D221.B4 D221.B5 D221.B6 D221.B7 D221.B8 D221.B9 D221.B10 D221.B11 D221.B12 D221.B13 D221.B14 D221.B15 D221.B16 D222.A1 D222.A2 D222.A3 D222.A4 D222.A5 D222.A6 D222.A7 D222.A8 D222.A9 D222.A10 D222.A11 D222.A12 D222.A13 D222.A14 D222.A15 D222.A16 D222.B1 D222.B2 D222.B3 D222.B4 D222.B5 D222.B6 D222.B7 D222.B8 D222.B9 D222.B10 D222.B11 D222.B12 D222.B13 D222.B14 D222.B15 D222.B16 D223.A1 D223.A2 D223.A3 D223.A4 D223.A5 D223.A6 D223.A7 D223.A8 D223.A9 D223.A10 D223.A11 D223.A12 D223.A13 D223.A14 D223.A15 D223.A16 D223.B1 D223.B2 D223.B3 D223.B4 D223.B5 D223.B6 D223.B7 D223.B8 D223.B9 D223.B10 D223.B11 D223.B12 D223.B13 D223.B14 D223.B15 D223.B16 D224.A1 D224.A2 D224.A3 D224.A4 D224.A5 D224.A6 D224.A7 D224.A8 D224.A9 D224.A10 D224.A11 D224.A12 D224.A13 D224.A14 D224.A15 D224.A16 D224.B1 D224.B2 D224.B3 D224.B4 D224.B5 D224.B6 D224.B7 D224.B8 D224.B9 D224.B10 D224.B11 D224.B12 D224.B13 D224.B14 D224.B15 D224.B16 D231.A1 D231.A2 D231.A3 D231.A4 D231.A5 D231.A6 D231.A7 D231.A8 D231.A9 D231.A10 D231.A11 D231.A12 D231.A13 D231.A14 D231.A15 D231.A16 D231.A17 D231.B1 D231.B2 D231.B3 D231.B4 D231.B5 D231.B6 D231.B7 D231.B8 D231.B9 D231.B10 D231.B11 D231.B12 D231.B13 D231.B14 D231.B15 D231.B16 D231.B17 D301.A1 D301.A2 D301.A3 D301.A4 D301.A5 D301.A6 D301.A7 D301.A8 D301.A9 D301.A10 D301.A11 D301.A12 D301.A13 D301.A14 D301.A15 D301.A16 D301.B1 D301.B2 D301.B3 D301.B4 D301.B5 D301.B6 D301.B7 D301.B8 D301.B9 D301.B10 D301.B11 D301.B12 D301.B13 D301.B14 D301.B15 D301.B16 D302.A1 D302.A2 D302.A3 D302.A4 D302.A5 D302.A6 D302.A7 D302.A8 D302.A9 D302.A10 D302.A11 D302.A12 D302.A13 D302.A14 D302.A15 D302.A16 D302.B1 D302.B2 D302.B3 D302.B4 D302.B5 D302.B6 D302.B7 D302.B8 D302.B9 D302.B10 D302.B11 D302.B12 D302.B13 D302.B14 D302.B15 D302.B16 D305.A1 D305.A2 D305.A3 D305.A4 D305.A5 D305.A6 D305.A7 D305.A8 D305.A9 D305.A10 D305.A11 D305.A12 D305.A13 D305.A14 D305.A15 D305.A16 D305.B1 D305.B2 D305.B3 D305.B4 D305.B5 D305.B6 D305.B7 D305.B8 D305.B9 D305.B10 D305.B11 D305.B12 D305.B13 D305.B14 D305.B15 D305.B16 D306.A1 D306.A2 D306.A3 D306.A4 D306.A5 D306.A6 D306.A7 D306.A8 D306.A9 D306.A10 D306.A11 D306.A12 D306.A13 D306.A14 D306.A15 D306.A16 D306.B1 D306.B2 D306.B3 D306.B4 D306.B5 D306.B6 D306.B7 D306.B8 D306.B9 D306.B10 D306.B11 D306.B12 D306.B13 D306.B14 D306.B15 D306.B16 D317.A1 D317.A2 D317.A3 D317.A4 D317.A5 D317.A6 D317.A7 D317.A8 D317.A9 D317.A10 D317.A11 D317.A12 D317.A13 D317.A14 D317.A15 D317.A16 D317.B1 D317.B2 D317.B3 D317.B4 D317.B5 D317.B6 D317.B7 D317.B8 D317.B9 D317.B10 D317.B11 D317.B12 D317.B13 D317.B14 D317.B15 D317.B16 D318.A1 D318.A2 D318.A3 D318.A4 D318.A5 D318.A6 D318.A7 D318.A8 D318.A9 D318.A10 D318.A11 D318.A12 D318.A13 D318.A14 D318.A15 D318.A16 D318.B1 D318.B2 D318.B3 D318.B4 D318.B5 D318.B6 D318.B7 D318.B8 D318.B9 D318.B10 D318.B11 D318.B12 D318.B13 D318.B14 D318.B15 D318.B16 D321.A1 D321.A2 D321.A3 D321.A4 D321.A5 D321.A6 D321.A7 D321.A8 D321.A9 D321.A10 D321.A11 D321.A12 D321.A13 D321.A14 D321.A15 D321.A16 D321.B1 D321.B2 D321.B3 D321.B4 D321.B5 D321.B6 D321.B7 D321.B8 D321.B9 D321.B10 D321.B11 D321.B12 D321.B13 D321.B14 D321.B15 D321.B16 D322.A1 D322.A2 D322.A3 D322.A4 D322.A5 D322.A6 D322.A7 D322.A8 D322.A9 D322.A10 D322.A11 D322.A12 D322.A13 D322.A14 D322.A15 D322.A16 D322.B1 D322.B2 D322.B3 D322.B4 D322.B5 D322.B6 D322.B7 D322.B8 D322.B9 D322.B10 D322.B11 D322.B12 D322.B13 D322.B14 D322.B15 D322.B16 D431.A1 D431.A2 D431.A3 D431.A4 D431.A5 D431.A6 D431.A7 D431.A8 D431.A9 D431.A10 D431.A11 D431.A12 D431.A13 D431.A14 D431.A15 D431.A16 D431.A17 D431.B1 D431.B2 D431.B3 D431.B4 D431.B5 D431.B6 D431.B7 D431.B8 D431.B9 D431.B10 D431.B11 D431.B12 D431.B13 D431.B14 D431.B15 D431.B16 D431.B17 DPS1.A01 DPS1.A05 DPS1.A11 DPS1.A15 DPS2.A01 DPS2.A05 DPS2.A11 DPS2.A15 DPS3.A01 DPS3.A05 DPS3.A11 DPS3.A15 DPS4.A01 DPS4.A05 DPS4.A11 DPS4.A15 DPS4.C01 DPS4.C05 DPS4.C11 DPS4.C15 DPS5.A01 DPS5.A05 DPS5.A11 DPS5.A15 DPS5.C01 DPS5.C05 DPS5.C11 DPS5.C15 DPS8.A01 DPS8.A05 DPS8.A11 DPS8.A15 GND1.1(TP) K54.G1 K54.G2 K54.G3 K54.G4 K54.G5 K54.G6 K54.G7 K54.G8 K54.G9 K54.G10 K60.G1 K60.G2 K60.G3 K60.G4 K60.G5 K60.G6 K60.G7 K60.G8 K60.G9 K60.G10 K61.G1 K61.G2 K61.G3 K61.G4 K61.G5 K61.G6 K61.G7 K61.G8 K61.G9 K61.G10 K62.G1 K62.G2 K62.G3 K62.G4 K62.G5 K62.G6 K62.G7 K62.G8 K62.G9 K62.G10 R51.1 R54.1 R163.1 R184.2 R185.2 SB1.1 SB2.1 SB3.1 SB8.1 SH2.2 SH4.2 SH5.2 SH8.2 SH9.2 SH11.2 SH13.2 SH15.2 SH17.2 SH19.2 SH21.2 SH23.2 SH25.2 SITE1.B4(VSS_CORE_09[1]) SITE1.B5(VSS_CORE_09[2]) SITE1.C12(VSS_CORE_09[3]) SITE1.C13(VSS_CORE_09[4]) SITE2.B4(VSS_CORE_09[1]) SITE2.B5(VSS_CORE_09[2]) SITE2.C12(VSS_CORE_09[3]) SITE2.C13(VSS_CORE_09[4]) SITE3.B4(VSS_CORE_09[1]) SITE3.B5(VSS_CORE_09[2]) SITE3.C12(VSS_CORE_09[3]) SITE3.C13(VSS_CORE_09[4]) SITE4.B4(VSS_CORE_09[1]) SITE4.B5(VSS_CORE_09[2]) SITE4.C12(VSS_CORE_09[3]) SITE4.C13(VSS_CORE_09[4]) U5.4(GND) UNK2C1.2 UNK2C55.1 UNK2C67.2 UNK2C69.2 UNK2C70.2 UNK2C71.2 UNK2C73.2 UNK2C75.2 UNK2C77.2 UNK2C79.2 UNK2C81.2 UNK2C83.2 UNK2C85.2 UNK2C87.2 UNK2C89.2 UNK2C90.2 UNK2C91.2 UNK2C92.2 UNK2C93.2 UNK2C94.2 UNK2C95.2 UNK2C96.2 UNK2CA1.2 UNK2CA2.2 UNK2CA3.2 UNK2CA4.2 UNK2CA5.2 UNK2CA6.2 UNK2CA7.2 UNK2CA8.2 UNK2CA9.2 UNK2CA10.2 UNK2CC1.2 UNK2CC2.2 UNK2CC3.2 UNK2CC4.2 UNK2CC5.2 UNK2CC6.2 UNK2CC7.2 UNK2CC8.2 UNK2CC9.2 UNK2CC10.2 UNK2CC11.2 UNK2CC12.2 UNK2CC13.2 UNK2CC14.2 UNK2CC15.2 UNK2CD1.2 UNK2CD2.2 UNK2CD3.2 UNK2CD4.2 UNK2CD5.2 UNK2CD6.2 UNK2CD7.2 UNK2CD8.2 UNK2CD9.2 UNK2CD10.2 UNK2CD11.2 UNK2CD12.2 UNK2CD13.2 UNK2CD14.2 UNK2CD15.2 UNK2GND1.1 UNK2K54.G1 UNK2K54.G2 UNK2K54.G3 UNK2K54.G4 UNK2K54.G5 UNK2K54.G6 UNK2K54.G7 UNK2K54.G8 UNK2K54.G9 UNK2K54.G10 UNK2K60.G1 UNK2K60.G2 UNK2K60.G3 UNK2K60.G4 UNK2K60.G5 UNK2K60.G6 UNK2K60.G7 UNK2K60.G8 UNK2K60.G9 UNK2K60.G10 UNK2K61.G1 UNK2K61.G2 UNK2K61.G3 UNK2K61.G4 UNK2K61.G5 UNK2K61.G6 UNK2K61.G7 UNK2K61.G8 UNK2K61.G9 UNK2K61.G10 UNK2K62.G1 UNK2K62.G2 UNK2K62.G3 UNK2K62.G4 UNK2K62.G5 UNK2K62.G6 UNK2K62.G7 UNK2K62.G8 UNK2K62.G9 UNK2K62.G10 UNK2R51.1 UNK2R54.1 UNK2R163.1 UNK2R184.2 UNK2R185.2 UNK2SH2.2 UNK2SH4.2 UNK2SH5.2 UNK2SH8.2 UNK2SH9.2 UNK2SH11.2 UNK2SH13.2 UNK2SH15.2 UNK2SH17.2 UNK2SH19.2 UNK2U5.4 UNK3C1.2 UNK3C55.1 UNK3C67.2 UNK3C69.2 UNK3C70.2 UNK3C71.2 UNK3C73.2 UNK3C75.2 UNK3C77.2 UNK3C79.2 UNK3C81.2 UNK3C83.2 UNK3C85.2 UNK3C87.2 UNK3C89.2 UNK3C90.2 UNK3C91.2 UNK3C92.2 UNK3C93.2 UNK3C94.2 UNK3C95.2 UNK3C96.2 UNK3CA1.2 UNK3CA2.2 UNK3CA3.2 UNK3CA4.2 UNK3CA5.2 UNK3CA6.2 UNK3CA7.2 UNK3CA8.2 UNK3CA9.2 UNK3CA10.2 UNK3CC1.2 UNK3CC2.2 UNK3CC3.2 UNK3CC4.2 UNK3CC5.2 UNK3CC6.2 UNK3CC7.2 UNK3CC8.2 UNK3CC9.2 UNK3CC10.2 UNK3CC11.2 UNK3CC12.2 UNK3CC13.2 UNK3CC14.2 UNK3CC15.2 UNK3CD1.2 UNK3CD2.2 UNK3CD3.2 UNK3CD4.2 UNK3CD5.2 UNK3CD6.2 UNK3CD7.2 UNK3CD8.2 UNK3CD9.2 UNK3CD10.2 UNK3CD11.2 UNK3CD12.2 UNK3CD13.2 UNK3CD14.2 UNK3CD15.2 UNK3GND1.1 UNK3K54.G1 UNK3K54.G2 UNK3K54.G3 UNK3K54.G4 UNK3K54.G5 UNK3K54.G6 UNK3K54.G7 UNK3K54.G8 UNK3K54.G9 UNK3K54.G10 UNK3K60.G1 UNK3K60.G2 UNK3K60.G3 UNK3K60.G4 UNK3K60.G5 UNK3K60.G6 UNK3K60.G7 UNK3K60.G8 UNK3K60.G9 UNK3K60.G10 UNK3K61.G1 UNK3K61.G2 UNK3K61.G3 UNK3K61.G4 UNK3K61.G5 UNK3K61.G6 UNK3K61.G7 UNK3K61.G8 UNK3K61.G9 UNK3K61.G10 UNK3K62.G1 UNK3K62.G2 UNK3K62.G3 UNK3K62.G4 UNK3K62.G5 UNK3K62.G6 UNK3K62.G7 UNK3K62.G8 UNK3K62.G9 UNK3K62.G10 UNK3R51.1 UNK3R54.1 UNK3R163.1 UNK3R184.2 UNK3R185.2 UNK3SH2.2 UNK3SH4.2 UNK3SH5.2 UNK3SH8.2 UNK3SH9.2 UNK3SH11.2 UNK3SH13.2 UNK3SH15.2 UNK3SH17.2 UNK3SH19.2 UNK3U5.4 UNK4C1.2 UNK4C55.1 UNK4C67.2 UNK4C69.2 UNK4C70.2 UNK4C71.2 UNK4C73.2 UNK4C75.2 UNK4C77.2 UNK4C79.2 UNK4C81.2 UNK4C83.2 UNK4C85.2 UNK4C87.2 UNK4C89.2 UNK4C90.2 UNK4C91.2 UNK4C92.2 UNK4C93.2 UNK4C94.2 UNK4C95.2 UNK4C96.2 UNK4CA1.2 UNK4CA2.2 UNK4CA3.2 UNK4CA4.2 UNK4CA5.2 UNK4CA6.2 UNK4CA7.2 UNK4CA8.2 UNK4CA9.2 UNK4CA10.2 UNK4CC1.2 UNK4CC2.2 UNK4CC3.2 UNK4CC4.2 UNK4CC5.2 UNK4CC6.2 UNK4CC7.2 UNK4CC8.2 UNK4CC9.2 UNK4CC10.2 UNK4CC11.2 UNK4CC12.2 UNK4CC13.2 UNK4CC14.2 UNK4CC15.2 UNK4CD1.2 UNK4CD2.2 UNK4CD3.2 UNK4CD4.2 UNK4CD5.2 UNK4CD6.2 UNK4CD7.2 UNK4CD8.2 UNK4CD9.2 UNK4CD10.2 UNK4CD11.2 UNK4CD12.2 UNK4CD13.2 UNK4CD14.2 UNK4CD15.2 UNK4GND1.1 UNK4K54.G1 UNK4K54.G2 UNK4K54.G3 UNK4K54.G4 UNK4K54.G5 UNK4K54.G6 UNK4K54.G7 UNK4K54.G8 UNK4K54.G9 UNK4K54.G10 UNK4K60.G1 UNK4K60.G2 UNK4K60.G3 UNK4K60.G4 UNK4K60.G5 UNK4K60.G6 UNK4K60.G7 UNK4K60.G8 UNK4K60.G9 UNK4K60.G10 UNK4K61.G1 UNK4K61.G2 UNK4K61.G3 UNK4K61.G4 UNK4K61.G5 UNK4K61.G6 UNK4K61.G7 UNK4K61.G8 UNK4K61.G9 UNK4K61.G10 UNK4K62.G1 UNK4K62.G2 UNK4K62.G3 UNK4K62.G4 UNK4K62.G5 UNK4K62.G6 UNK4K62.G7 UNK4K62.G8 UNK4K62.G9 UNK4K62.G10 UNK4R51.1 UNK4R54.1 UNK4R163.1 UNK4R184.2 UNK4R185.2 UNK4SH2.2 UNK4SH4.2 UNK4SH5.2 UNK4SH8.2 UNK4SH9.2 UNK4SH11.2 UNK4SH13.2 UNK4SH15.2 UNK4SH17.2 UNK4SH19.2 UNK4U5.4
CSDPS225GS1: CSDPS225.D2
CSDPS225GS2: CSDPS225.A1
CSDPS225GS3: CSDPS225.D4
CSDPS225GS4: CSDPS225.A3
CSDPS225GS5: CSDPS225.D6
CSDPS225GS6: CSDPS225.A5
CSDPS225GS7: CSDPS225.D8
CSDPS225GS8: CSDPS225.A7
CSDPS225GS9: CSDPS225.D10
CSDPS225GS10: CSDPS225.A9
CSDPS225GS11: CSDPS225.D12
CSDPS225GS12: CSDPS225.A11
CSDPS225GS13: CSDPS225.D14
CSDPS225GS14: CSDPS225.A13
CSDPS225GS15: CSDPS225.D16
CSDPS225GS16: CSDPS225.A15
CSDPS225P1: CSDPS225.B1
CSDPS225P2: CSDPS225.C2
CSDPS225P3: CSDPS225.B3
CSDPS225P4: CSDPS225.C4
CSDPS225P5: CSDPS225.B5
CSDPS225P6: CSDPS225.C6
CSDPS225P7: CSDPS225.B7
CSDPS225P8: CSDPS225.C8
CSDPS225P9: CSDPS225.B9
CSDPS225P10: CSDPS225.C10
CSDPS225P11: CSDPS225.B11
CSDPS225P12: CSDPS225.C12
CSDPS225P13: CSDPS225.B13
CSDPS225P14: CSDPS225.C14
CSDPS225P15: CSDPS225.B15
CSDPS225P16: CSDPS225.C16
CSDPS225PS1: CSDPS225.D1
CSDPS225PS2: CSDPS225.A2
CSDPS225PS3: CSDPS225.D3
CSDPS225PS4: CSDPS225.A4
CSDPS225PS5: CSDPS225.D5
CSDPS225PS6: CSDPS225.A6
CSDPS225PS7: CSDPS225.D7
CSDPS225PS8: CSDPS225.A8
CSDPS225PS9: CSDPS225.D9
CSDPS225PS10: CSDPS225.A10
CSDPS225PS11: CSDPS225.D11
CSDPS225PS12: CSDPS225.A12
CSDPS225PS13: CSDPS225.D13
CSDPS225PS14: CSDPS225.A14
CSDPS225PS15: CSDPS225.D15
CSDPS225PS16: CSDPS225.A16
CSDPS229GS1: CSDPS229.D2
CSDPS229GS2: CSDPS229.A1
CSDPS229GS3: CSDPS229.D4
CSDPS229GS4: CSDPS229.A3
CSDPS229GS5: CSDPS229.D6
CSDPS229GS6: CSDPS229.A5
CSDPS229GS7: CSDPS229.D8
CSDPS229GS8: CSDPS229.A7
CSDPS229GS9: CSDPS229.D10
CSDPS229GS10: CSDPS229.A9
CSDPS229GS11: CSDPS229.D12
CSDPS229GS12: CSDPS229.A11
CSDPS229GS13: CSDPS229.D14
CSDPS229GS14: CSDPS229.A13
CSDPS229GS15: CSDPS229.D16
CSDPS229GS16: CSDPS229.A15
CSDPS229P1: CSDPS229.B1
CSDPS229P2: CSDPS229.C2
CSDPS229P3: CSDPS229.B3
CSDPS229P4: CSDPS229.C4
CSDPS229P5: CSDPS229.B5
CSDPS229P6: CSDPS229.C6
CSDPS229P7: CSDPS229.B7
CSDPS229P8: CSDPS229.C8
CSDPS229P9: CSDPS229.B9
CSDPS229P10: CSDPS229.C10
CSDPS229P11: CSDPS229.B11
CSDPS229P12: CSDPS229.C12
CSDPS229P13: CSDPS229.B13
CSDPS229P14: CSDPS229.C14
CSDPS229P15: CSDPS229.B15
CSDPS229P16: CSDPS229.C16
CSDPS229PS1: CSDPS229.D1
CSDPS229PS2: CSDPS229.A2
CSDPS229PS3: CSDPS229.D3
CSDPS229PS4: CSDPS229.A4
CSDPS229PS5: CSDPS229.D5
CSDPS229PS6: CSDPS229.A6
CSDPS229PS7: CSDPS229.D7
CSDPS229PS8: CSDPS229.A8
CSDPS229PS9: CSDPS229.D9
CSDPS229PS10: CSDPS229.A10
CSDPS229PS11: CSDPS229.D11
CSDPS229PS12: CSDPS229.A12
CSDPS229PS13: CSDPS229.D13
CSDPS229PS14: CSDPS229.A14
CSDPS229PS15: CSDPS229.D15
CSDPS229PS16: CSDPS229.A16
CSDPS425GS1: CSDPS425.D2
CSDPS425GS2: CSDPS425.A1
CSDPS425GS3: CSDPS425.D4
CSDPS425GS4: CSDPS425.A3
CSDPS425GS5: CSDPS425.D6
CSDPS425GS6: CSDPS425.A5
CSDPS425GS7: CSDPS425.D8
CSDPS425GS8: CSDPS425.A7
CSDPS425GS9: CSDPS425.D10
CSDPS425GS10: CSDPS425.A9
CSDPS425GS11: CSDPS425.D12
CSDPS425GS12: CSDPS425.A11
CSDPS425GS13: CSDPS425.D14
CSDPS425GS14: CSDPS425.A13
CSDPS425GS15: CSDPS425.D16
CSDPS425GS16: CSDPS425.A15
CSDPS425P1: CSDPS425.B1
CSDPS425P2: CSDPS425.C2
CSDPS425P3: CSDPS425.B3
CSDPS425P4: CSDPS425.C4
CSDPS425P5: CSDPS425.B5
CSDPS425P6: CSDPS425.C6
CSDPS425P7: CSDPS425.B7
CSDPS425P8: CSDPS425.C8
CSDPS425P9: CSDPS425.B9
CSDPS425P10: CSDPS425.C10
CSDPS425P11: CSDPS425.B11
CSDPS425P12: CSDPS425.C12
CSDPS425P13: CSDPS425.B13
CSDPS425P14: CSDPS425.C14
CSDPS425P15: CSDPS425.B15
CSDPS425P16: CSDPS425.C16
CSDPS425PS1: CSDPS425.D1
CSDPS425PS2: CSDPS425.A2
CSDPS425PS3: CSDPS425.D3
CSDPS425PS4: CSDPS425.A4
CSDPS425PS5: CSDPS425.D5
CSDPS425PS6: CSDPS425.A6
CSDPS425PS7: CSDPS425.D7
CSDPS425PS8: CSDPS425.A8
CSDPS425PS9: CSDPS425.D9
CSDPS425PS10: CSDPS425.A10
CSDPS425PS11: CSDPS425.D11
CSDPS425PS12: CSDPS425.A12
CSDPS425PS13: CSDPS425.D13
CSDPS425PS14: CSDPS425.A14
CSDPS425PS15: CSDPS425.D15
CSDPS425PS16: CSDPS425.A16
CSDPS429GS1: CSDPS429.D2
CSDPS429GS2: CSDPS429.A1
CSDPS429GS3: CSDPS429.D4
CSDPS429GS4: CSDPS429.A3
CSDPS429GS5: CSDPS429.D6
CSDPS429GS6: CSDPS429.A5
CSDPS429GS7: CSDPS429.D8
CSDPS429GS8: CSDPS429.A7
CSDPS429GS9: CSDPS429.D10
CSDPS429GS10: CSDPS429.A9
CSDPS429GS11: CSDPS429.D12
CSDPS429GS12: CSDPS429.A11
CSDPS429GS13: CSDPS429.D14
CSDPS429GS14: CSDPS429.A13
CSDPS429GS15: CSDPS429.D16
CSDPS429GS16: CSDPS429.A15
CSDPS429P1: CSDPS429.B1
CSDPS429P2: CSDPS429.C2
CSDPS429P3: CSDPS429.B3
CSDPS429P4: CSDPS429.C4
CSDPS429P5: CSDPS429.B5
CSDPS429P6: CSDPS429.C6
CSDPS429P7: CSDPS429.B7
CSDPS429P8: CSDPS429.C8
CSDPS429P9: CSDPS429.B9
CSDPS429P10: CSDPS429.C10
CSDPS429P11: CSDPS429.B11
CSDPS429P12: CSDPS429.C12
CSDPS429P13: CSDPS429.B13
CSDPS429P14: CSDPS429.C14
CSDPS429P15: CSDPS429.B15
CSDPS429P16: CSDPS429.C16
CSDPS429PS1: CSDPS429.D1
CSDPS429PS2: CSDPS429.A2
CSDPS429PS3: CSDPS429.D3
CSDPS429PS4: CSDPS429.A4
CSDPS429PS5: CSDPS429.D5
CSDPS429PS6: CSDPS429.A6
CSDPS429PS7: CSDPS429.D7
CSDPS429PS8: CSDPS429.A8
CSDPS429PS9: CSDPS429.D9
CSDPS429PS10: CSDPS429.A10
CSDPS429PS11: CSDPS429.D11
CSDPS429PS12: CSDPS429.A12
CSDPS429PS13: CSDPS429.D13
CSDPS429PS14: CSDPS429.A14
CSDPS429PS15: CSDPS429.D15
CSDPS429PS16: CSDPS429.A16
D231_MCB1_E+: D231.16
D231_MCB1_E-: D231.15
D231_MCB1_EE+: D231.08
D231_MCB1_EE-: D231.07
D231_MCB1_F+: D231.14
D231_MCB1_F-: D231.13
D231_MCB1_FF+: D231.06
D231_MCB1_FF-: D231.05
D231_MCB1_G+: D231.12
D231_MCB1_G-: D231.11
D231_MCB1_GG+: D231.04
D231_MCB1_GG-: D231.03
D231_MCB1_H+: D231.10
D231_MCB1_H-: D231.09
D231_MCB1_HH+: D231.02
D231_MCB1_HH-: D231.01
D10401: D104.01
D10402: D104.02
D10403: D104.03
D10404: D104.04
D10405: D104.05
D10406: D104.06
D10407: D104.07
D10408: D104.08
D10409: D104.09
D10410: D104.10
D10411: D104.11
D10412: D104.12
D10413: D104.13
D10414: D104.14
D10415: D104.15
D10416: D104.16
D10801: D108.01
D10802: D108.02
D10803: D108.03
D10804: D108.04
D10805: D108.05
D10806: D108.06
D10807: D108.07
D10808: D108.08
D10809: D108.09
D10810: D108.10
D10811: D108.11
D10812: D108.12
D10813: D108.13
D10814: D108.14
D10815: D108.15
D10816: D108.16
D10901: D109.01
D10902: D109.02
D10903: D109.03
D10904: D109.04
D10905: D109.05
D10906: D109.06
D10907: D109.07
D10908: D109.08
D10909: D109.09
D10910: D109.10
D10911: D109.11
D10912: D109.12
D10913: D109.13
D10914: D109.14
D10915: D109.15
D10916: D109.16
D11001: D110.01
D11002: D110.02
D11003: D110.03
D11004: D110.04
D11005: D110.05
D11006: D110.06
D11007: D110.07
D11008: D110.08
D11009: D110.09
D11010: D110.10
D11011: D110.11
D11012: D110.12
D11013: D110.13
D11014: D110.14
D11015: D110.15
D11016: D110.16
D11101: D111.01
D11102: D111.02
D11103: D111.03
D11104: D111.04
D11105: D111.05
D11106: D111.06
D11107: D111.07
D11108: D111.08
D11109: D111.09
D11110: D111.10
D11111: D111.11
D11112: D111.12
D11113: D111.13
D11114: D111.14
D11115: D111.15
D11116: D111.16
D11201: D112.01
D11202: D112.02
D11203: D112.03
D11204: D112.04
D11205: D112.05
D11206: D112.06
D11207: D112.07
D11208: D112.08
D11209: D112.09
D11210: D112.10
D11211: D112.11
D11212: D112.12
D11213: D112.13
D11214: D112.14
D11215: D112.15
D11216: D112.16
D11301: D113.01
D11302: D113.02
D11303: D113.03
D11304: D113.04
D11305: D113.05
D11306: D113.06
D11307: D113.07
D11308: D113.08
D11309: D113.09
D11310: D113.10
D11311: D113.11
D11312: D113.12
D11313: D113.13
D11314: D113.14
D11315: D113.15
D11316: D113.16
D11401: D114.01
D11402: D114.02
D11403: D114.03
D11404: D114.04
D11405: D114.05
D11406: D114.06
D11407: D114.07
D11408: D114.08
D11409: D114.09
D11410: D114.10
D11411: D114.11
D11412: D114.12
D11413: D114.13
D11414: D114.14
D11415: D114.15
D11416: D114.16
D11501: D115.01
D11502: D115.02
D11503: D115.03
D11504: D115.04
D11505: D115.05
D11506: D115.06
D11507: D115.07
D11508: D115.08
D11509: D115.09
D11510: D115.10
D11511: D115.11
D11512: D115.12
D11513: D115.13
D11514: D115.14
D11515: D115.15
D11516: D115.16
D11601: D116.01
D11602: D116.02
D11603: D116.03
D11604: D116.04
D11605: D116.05
D11606: D116.06
D11607: D116.07
D11608: D116.08
D11609: D116.09
D11610: D116.10
D11611: D116.11
D11612: D116.12
D11613: D116.13
D11614: D116.14
D11615: D116.15
D11616: D116.16 D231.17
D12001: D120.01
D12002: D120.02
D12003: D120.03
D12004: D120.04
D12005: D120.05
D12006: D120.06
D12007: D120.07
D12008: D120.08
D12009: D120.09
D12010: D120.10
D12011: D120.11
D12012: D120.12
D12013: D120.13
D12014: D120.14
D12015: D120.15
D12016: D120.16
D12401: D124.01
D12402: D124.02
D12403: D124.03
D12404: D124.04
D12405: D124.05
D12406: D124.06
D12407: D124.07
D12408: D124.08
D12409: D124.09
D12410: D124.10 SB12.2
D12411: D124.11 SB11.2
D12412: D124.12
D12413: D124.13
D12414: D124.14
D12415: D124.15
D12416: D124.16
D12501: D125.01
D12502: D125.02
D12503: D125.03
D12504: D125.04
D12505: D125.05
D12506: D125.06
D12507: D125.07
D12508: D125.08
D12509: D125.09
D12510: D125.10
D12511: D125.11
D12512: D125.12
D12513: D125.13
D12514: D125.14
D12515: D125.15
D12516: D125.16
D12601: D126.01
D12602: D126.02
D12603: D126.03
D12604: D126.04
D12605: D126.05
D12606: D126.06
D12607: D126.07
D12608: D126.08
D12609: D126.09
D12610: D126.10
D12611: D126.11
D12612: D126.12
D12613: D126.13
D12614: D126.14
D12615: D126.15
D12616: D126.16
D12701: D127.01
D12702: D127.02
D12703: D127.03
D12704: D127.04
D12705: D127.05
D12706: D127.06
D12707: D127.07
D12708: D127.08
D12709: D127.09
D12710: D127.10
D12711: D127.11
D12712: D127.12
D12713: D127.13
D12714: D127.14
D12715: D127.15
D12716: D127.16
D12801: D128.01
D12802: D128.02
D12803: D128.03
D12804: D128.04
D12805: D128.05
D12806: D128.06
D12807: D128.07
D12808: D128.08
D12809: D128.09
D12810: D128.10
D12811: D128.11
D12812: D128.12
D12813: D128.13
D12814: D128.14
D12815: D128.15
D12816: D128.16
D12901: D129.01
D12902: D129.02
D12903: D129.03
D12904: D129.04
D12905: D129.05
D12906: D129.06
D12907: D129.07
D12908: D129.08
D12909: D129.09
D12910: D129.10
D12911: D129.11
D12912: D129.12
D12913: D129.13
D12914: D129.14
D12915: D129.15
D12916: D129.16
D13001: D130.01
D13002: D130.02
D13003: D130.03
D13004: D130.04
D13005: D130.05
D13006: D130.06
D13007: D130.07
D13008: D130.08
D13009: D130.09
D13010: D130.10
D13011: D130.11
D13012: D130.12
D13013: D130.13
D13014: D130.14
D13015: D130.15
D13016: D130.16
D13101: D131.01
D13102: D131.02
D13103: D131.03
D13104: D131.04
D13105: D131.05
D13106: D131.06
D13107: D131.07
D13108: D131.08
D13109: D131.09
D13110: D131.10
D13111: D131.11
D13112: D131.12
D13113: D131.13
D13114: D131.14
D13115: D131.15
D13116: D131.16
D13201: D132.01
D13202: D132.02
D13203: D132.03
D13204: D132.04
D13205: D132.05
D13206: D132.06
D13207: D132.07
D13208: D132.08
D13209: D132.09
D13210: D132.10
D13211: D132.11
D13212: D132.12
D13213: D132.13
D13214: D132.14
D13215: D132.15
D13216: D132.16
D20101: D201.01
D20102: D201.02
D20103: D201.03
D20104: D201.04
D20105: D201.05
D20106: D201.06
D20107: D201.07
D20108: D201.08
D20109: D201.09
D20110: D201.10
D20111: D201.11
D20112: D201.12
D20113: D201.13
D20114: D201.14
D20115: D201.15
D20116: D201.16
D20201: D202.01
D20202: D202.02
D20203: D202.03
D20204: D202.04
D20205: D202.05
D20206: D202.06
D20207: D202.07
D20208: D202.08
D20209: D202.09
D20210: D202.10
D20211: D202.11
D20212: D202.12
D20213: D202.13
D20214: D202.14
D20215: D202.15
D20216: D202.16
D20301: D203.01
D20302: D203.02
D20303: D203.03
D20304: D203.04
D20305: D203.05
D20306: D203.06
D20307: D203.07
D20308: D203.08
D20309: D203.09
D20310: D203.10
D20311: D203.11
D20312: D203.12
D20313: D203.13
D20314: D203.14
D20315: D203.15
D20316: D203.16
D20401: D204.01
D20402: D204.02
D20403: D204.03
D20404: D204.04
D20405: D204.05
D20406: D204.06
D20407: D204.07
D20408: D204.08
D20409: D204.09
D20410: D204.10
D20411: D204.11
D20412: D204.12
D20413: D204.13
D20414: D204.14
D20415: D204.15
D20416: D204.16
D20501: D205.01
D20502: D205.02
D20503: D205.03
D20504: D205.04
D20505: D205.05
D20506: D205.06
D20507: D205.07
D20508: D205.08
D20509: D205.09
D20510: D205.10
D20511: D205.11
D20512: D205.12
D20513: D205.13
D20514: D205.14
D20515: D205.15
D20516: D205.16
D20601: D206.01
D20602: D206.02
D20603: D206.03
